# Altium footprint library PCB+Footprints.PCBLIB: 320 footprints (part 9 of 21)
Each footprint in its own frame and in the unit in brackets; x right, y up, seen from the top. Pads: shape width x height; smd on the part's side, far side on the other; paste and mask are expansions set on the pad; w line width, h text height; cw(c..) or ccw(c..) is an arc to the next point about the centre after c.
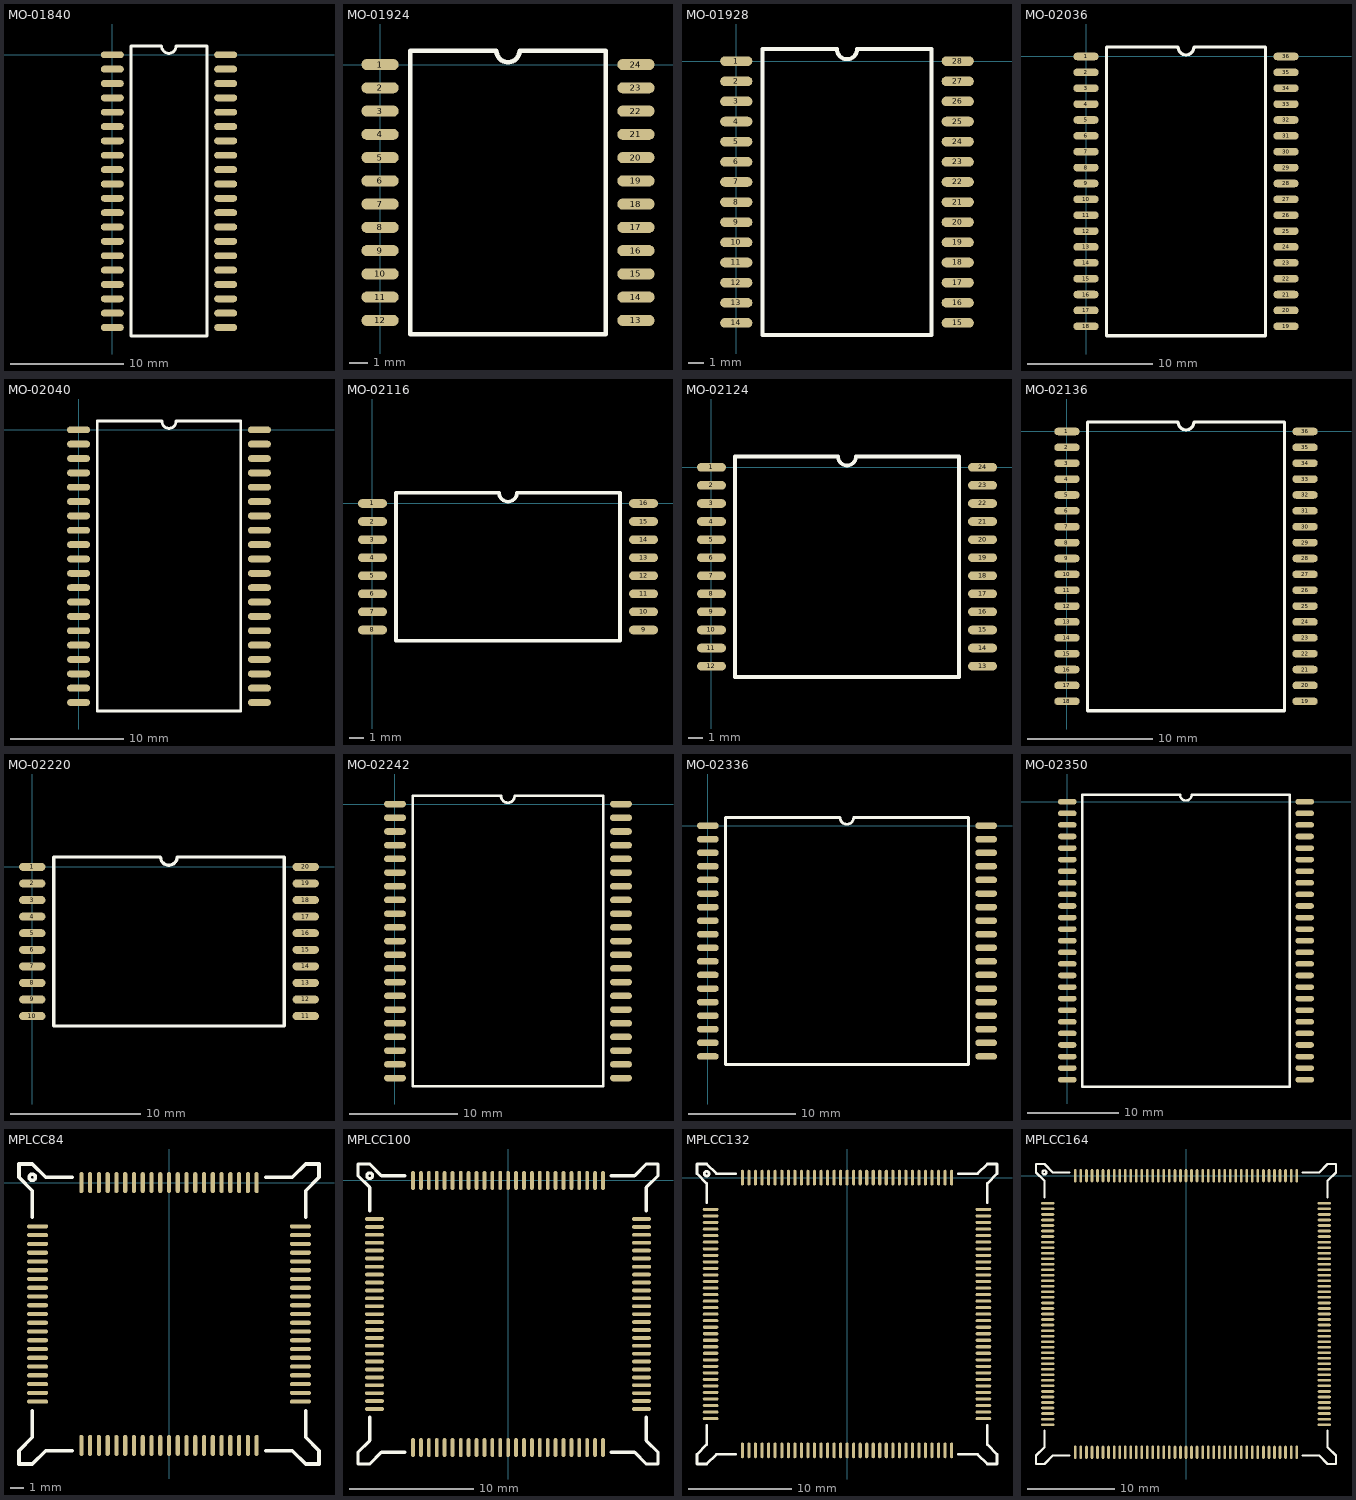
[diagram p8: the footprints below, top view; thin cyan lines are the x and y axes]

## MO-01840 [mil]
pads (40):
  oval 80x24 smd: 1(0,0) 2(0,-50) 3(0,-100) 4(0,-150) 5(0,-200) 6(0,-250) 7(0,-300) 8(0,-350) 9(0,-400) 10(0,-450) 11(0,-500) 12(0,-550) 13(0,-600) 14(0,-650) 15(0,-700) 16(0,-750) 17(0,-800) 18(0,-850) 19(0,-900) 20(0,-950) 21(395,-950) 22(395,-900) 23(395,-850) 24(395,-800) 25(395,-750) 26(395,-700) 27(395,-650) 28(395,-600) 29(395,-550) 30(395,-500) 31(395,-450) 32(395,-400) 33(395,-350) 34(395,-300) 35(395,-250) 36(395,-200) 37(395,-150) 38(395,-100) 39(395,-50) 40(395,0)
TopOverlay:
  lines w10: 65,-980 65,30 172,30 ccw(c197,30) 222,30 330,30 330,-980 65,-980

## MO-01924 [mil]
pads (24):
  oval 80x24 smd: 1(0,0) 2(0,-50) 3(0,-100) 4(0,-150) 5(0,-200) 6(0,-250) 7(0,-300) 8(0,-350) 9(0,-400) 10(0,-450) 11(0,-500) 12(0,-550) 13(550,-550) 14(550,-500) 15(550,-450) 16(550,-400) 17(550,-350) 18(550,-300) 19(550,-250) 20(550,-200) 21(550,-150) 22(550,-100) 23(550,-50) 24(550,0)
TopOverlay:
  lines w10: 65,-580 485,-580 485,30 300,30 cw(c275,30) 250,30 65,30 65,-580

## MO-01928 [mil]
pads (28):
  oval 80x24 smd: 1(0,0) 2(0,-50) 3(0,-100) 4(0,-150) 5(0,-200) 6(0,-250) 7(0,-300) 8(0,-350) 9(0,-400) 10(0,-450) 11(0,-500) 12(0,-550) 13(0,-600) 14(0,-650) 15(550,-650) 16(550,-600) 17(550,-550) 18(550,-500) 19(550,-450) 20(550,-400) 21(550,-350) 22(550,-300) 23(550,-250) 24(550,-200) 25(550,-150) 26(550,-100) 27(550,-50) 28(550,0)
TopOverlay:
  lines w10: 65,-680 485,-680 485,30 300,30 cw(c275,30) 250,30 65,30 65,-680

## MO-02036 [mil]
pads (36):
  oval 80x24 smd: 1(0,0) 2(0,-50) 3(0,-100) 4(0,-150) 5(0,-200) 6(0,-250) 7(0,-300) 8(0,-350) 9(0,-400) 10(0,-450) 11(0,-500) 12(0,-550) 13(0,-600) 14(0,-650) 15(0,-700) 16(0,-750) 17(0,-800) 18(0,-850) 19(630,-850) 20(630,-800) 21(630,-750) 22(630,-700) 23(630,-650) 24(630,-600) 25(630,-550) 26(630,-500) 27(630,-450) 28(630,-400) 29(630,-350) 30(630,-300) 31(630,-250) 32(630,-200) 33(630,-150) 34(630,-100) 35(630,-50) 36(630,0)
TopOverlay:
  lines w10: 65,-880 565,-880 565,30 340,30 cw(c315,30) 290,30 65,30 65,-880

## MO-02040 [mil]
pads (40):
  oval 80x24 smd: 1(0,0) 2(0,-50) 3(0,-100) 4(0,-150) 5(0,-200) 6(0,-250) 7(0,-300) 8(0,-350) 9(0,-400) 10(0,-450) 11(0,-500) 12(0,-550) 13(0,-600) 14(0,-650) 15(0,-700) 16(0,-750) 17(0,-800) 18(0,-850) 19(0,-900) 20(0,-950) 21(630,-950) 22(630,-900) 23(630,-850) 24(630,-800) 25(630,-750) 26(630,-700) 27(630,-650) 28(630,-600) 29(630,-550) 30(630,-500) 31(630,-450) 32(630,-400) 33(630,-350) 34(630,-300) 35(630,-250) 36(630,-200) 37(630,-150) 38(630,-100) 39(630,-50) 40(630,0)
TopOverlay:
  lines w10: 65,-980 565,-980 565,30 340,30 cw(c315,30) 290,30 65,30 65,-980

## MO-02116 [mil]
pads (16):
  oval 80x24 smd: 1(0,0) 2(0,-50) 3(0,-100) 4(0,-150) 5(0,-200) 6(0,-250) 7(0,-300) 8(0,-350) 9(750,-350) 10(750,-300) 11(750,-250) 12(750,-200) 13(750,-150) 14(750,-100) 15(750,-50) 16(750,0)
TopOverlay:
  lines w10: 65,-380 685,-380 685,30 400,30 cw(c375,30) 350,30 65,30 65,-380

## MO-02124 [mil]
pads (24):
  oval 80x24 smd: 1(0,0) 2(0,-50) 3(0,-100) 4(0,-150) 5(0,-200) 6(0,-250) 7(0,-300) 8(0,-350) 9(0,-400) 10(0,-450) 11(0,-500) 12(0,-550) 13(750,-550) 14(750,-500) 15(750,-450) 16(750,-400) 17(750,-350) 18(750,-300) 19(750,-250) 20(750,-200) 21(750,-150) 22(750,-100) 23(750,-50) 24(750,0)
TopOverlay:
  lines w10: 65,-580 685,-580 685,30 400,30 cw(c375,30) 350,30 65,30 65,-580

## MO-02136 [mil]
pads (36):
  oval 80x24 smd: 1(0,0) 2(0,-50) 3(0,-100) 4(0,-150) 5(0,-200) 6(0,-250) 7(0,-300) 8(0,-350) 9(0,-400) 10(0,-450) 11(0,-500) 12(0,-550) 13(0,-600) 14(0,-650) 15(0,-700) 16(0,-750) 17(0,-800) 18(0,-850) 19(750,-850) 20(750,-800) 21(750,-750) 22(750,-700) 23(750,-650) 24(750,-600) 25(750,-550) 26(750,-500) 27(750,-450) 28(750,-400) 29(750,-350) 30(750,-300) 31(750,-250) 32(750,-200) 33(750,-150) 34(750,-100) 35(750,-50) 36(750,0)
TopOverlay:
  lines w10: 65,-880 685,-880 685,30 400,30 cw(c375,30) 350,30 65,30 65,-880

## MO-02220 [mil]
pads (20):
  oval 80x24 smd: 1(0,0) 2(0,-50) 3(0,-100) 4(0,-150) 5(0,-200) 6(0,-250) 7(0,-300) 8(0,-350) 9(0,-400) 10(0,-450) 11(825,-450) 12(825,-400) 13(825,-350) 14(825,-300) 15(825,-250) 16(825,-200) 17(825,-150) 18(825,-100) 19(825,-50) 20(825,0)
TopOverlay:
  lines w10: 65,-480 760,-480 760,30 437,30 cw(c412,30) 387,30 65,30 65,-480

## MO-02242 [mil]
pads (42):
  oval 80x24 smd: 1(0,0) 2(0,-50) 3(0,-100) 4(0,-150) 5(0,-200) 6(0,-250) 7(0,-300) 8(0,-350) 9(0,-400) 10(0,-450) 11(0,-500) 12(0,-550) 13(0,-600) 14(0,-650) 15(0,-700) 16(0,-750) 17(0,-800) 18(0,-850) 19(0,-900) 20(0,-950) 21(0,-1000) 22(825,-1000) 23(825,-950) 24(825,-900) 25(825,-850) 26(825,-800) 27(825,-750) 28(825,-700) 29(825,-650) 30(825,-600) 31(825,-550) 32(825,-500) 33(825,-450) 34(825,-400) 35(825,-350) 36(825,-300) 37(825,-250) 38(825,-200) 39(825,-150) 40(825,-100) 41(825,-50) 42(825,0)
TopOverlay:
  lines w10: 65,-1030 760,-1030 760,30 437,30 cw(c412,30) 387,30 65,30 65,-1030

## MO-02336 [mil]
pads (36):
  oval 80x24 smd: 1(0,0) 2(0,-50) 3(0,-100) 4(0,-150) 5(0,-200) 6(0,-250) 7(0,-300) 8(0,-350) 9(0,-400) 10(0,-450) 11(0,-500) 12(0,-550) 13(0,-600) 14(0,-650) 15(0,-700) 16(0,-750) 17(0,-800) 18(0,-850) 19(1025,-850) 20(1025,-800) 21(1025,-750) 22(1025,-700) 23(1025,-650) 24(1025,-600) 25(1025,-550) 26(1025,-500) 27(1025,-450) 28(1025,-400) 29(1025,-350) 30(1025,-300) 31(1025,-250) 32(1025,-200) 33(1025,-150) 34(1025,-100) 35(1025,-50) 36(1025,0)
TopOverlay:
  lines w10: 65,-880 960,-880 960,30 537,30 cw(c512,30) 487,30 65,30 65,-880

## MO-02350 [mil]
pads (50):
  oval 80x24 smd: 1(0,0) 2(0,-50) 3(0,-100) 4(0,-150) 5(0,-200) 6(0,-250) 7(0,-300) 8(0,-350) 9(0,-400) 10(0,-450) 11(0,-500) 12(0,-550) 13(0,-600) 14(0,-650) 15(0,-700) 16(0,-750) 17(0,-800) 18(0,-850) 19(0,-900) 20(0,-950) 21(0,-1000) 22(0,-1050) 23(0,-1100) 24(0,-1150) 25(0,-1200) 26(1025,-1200) 27(1025,-1150) 28(1025,-1100) 29(1025,-1050) 30(1025,-1000) 31(1025,-950) 32(1025,-900) 33(1025,-850) 34(1025,-800) 35(1025,-750) 36(1025,-700) 37(1025,-650) 38(1025,-600) 39(1025,-550) 40(1025,-500) 41(1025,-450) 42(1025,-400) 43(1025,-350) 44(1025,-300) 45(1025,-250) 46(1025,-200) 47(1025,-150) 48(1025,-100) 49(1025,-50) 50(1025,0)
TopOverlay:
  lines w10: 65,-1230 960,-1230 960,30 537,30 cw(c512,30) 487,30 65,30 65,-1230

## MPLCC84 [mil]
pads (84):
  oval 12x60 smd: 1(0,0) 2(-25,0) 3(-50,0) 4(-75,0) 5(-100,0) 6(-125,0) 7(-150,0) 8(-175,0) 9(-200,0) 10(-225,0) 11(-250,0) 33(-250,-750) 34(-225,-750) 35(-200,-750) 36(-175,-750) 37(-150,-750) 38(-125,-750) 39(-100,-750) 40(-75,-750) 41(-50,-750) 42(-25,-750) 43(0,-750) 44(25,-750) 45(50,-750) 46(75,-750) 47(100,-750) 48(125,-750) 49(150,-750) 50(175,-750) 51(200,-750) 52(225,-750) 53(250,-750) 75(250,0) 76(225,0) 77(200,0) 78(175,0) 79(150,0) 80(125,0) 81(100,0) 82(75,0) 83(50,0) 84(25,0)
  oval 60x12 smd: 12(-375,-125) 13(-375,-150) 14(-375,-175) 15(-375,-200) 16(-375,-225) 17(-375,-250) 18(-375,-275) 19(-375,-300) 20(-375,-325) 21(-375,-350) 22(-375,-375) 23(-375,-400) 24(-375,-425) 25(-375,-450) 26(-375,-475) 27(-375,-500) 28(-375,-525) 29(-375,-550) 30(-375,-575) 31(-375,-600) 32(-375,-625) 54(375,-625) 55(375,-600) 56(375,-575) 57(375,-550) 58(375,-525) 59(375,-500) 60(375,-475) 61(375,-450) 62(375,-425) 63(375,-400) 64(375,-375) 65(375,-350) 66(375,-325) 67(375,-300) 68(375,-275) 69(375,-250) 70(375,-225) 71(375,-200) 72(375,-175) 73(375,-150) 74(375,-125)
TopOverlay:
  circle w10: c-390,15 r9
  lines w10: -390,-651 -390,-727 -428,-765 -428,-803 -390,-803 -352,-765 -276,-765 ; -390,-99 -390,-23 -428,15 -428,53 -390,53 -352,15 -276,15 ; 276,-765 352,-765 390,-803 428,-803 428,-765 390,-727 390,-651 ; 276,15 352,15 390,53 428,53 428,15 390,-23 390,-99

## MPLCC100 [mil]
pads (100):
  oval 12x60 smd: 1(0,0) 2(-25,0) 3(-50,0) 4(-75,0) 5(-100,0) 6(-125,0) 7(-150,0) 8(-176,0) 9(-201,0) 10(-226,0) 11(-251,0) 12(-276,0) 13(-301,0) 39(-301,-845) 40(-276,-845) 41(-251,-845) 42(-226,-845) 43(-201,-845) 44(-176,-845) 45(-150,-845) 46(-125,-845) 47(-100,-845) 48(-75,-845) 49(-50,-845) 50(-25,-845) 51(0,-845) 52(25,-845) 53(50,-845) 54(75,-845) 55(100,-845) 56(125,-845) 57(150,-845) 58(175,-845) 59(200,-845) 60(225,-845) 61(250,-845) 62(275,-845) 63(300,-845) 89(300,0) 90(275,0) 91(250,0) 92(225,0) 93(200,0) 94(175,0) 95(150,0) 96(125,0) 97(100,0) 98(75,0) 99(50,0) 100(25,0)
  oval 60x12 smd: 14(-423,-122) 15(-423,-147) 16(-423,-172) 17(-423,-197) 18(-423,-222) 19(-423,-247) 20(-423,-273) 21(-423,-298) 22(-423,-323) 23(-423,-348) 24(-423,-373) 25(-423,-398) 26(-423,-423) 27(-423,-448) 28(-423,-473) 29(-423,-498) 30(-423,-523) 31(-423,-548) 32(-423,-573) 33(-423,-598) 34(-423,-623) 35(-423,-648) 36(-423,-673) 37(-423,-698) 38(-423,-723) 64(422,-723) 65(422,-698) 66(422,-673) 67(422,-648) 68(422,-623) 69(422,-598) 70(422,-573) 71(422,-548) 72(422,-523) 73(422,-498) 74(422,-473) 75(422,-448) 76(422,-423) 77(422,-398) 78(422,-373) 79(422,-348) 80(422,-323) 81(422,-298) 82(422,-273) 83(422,-247) 84(422,-222) 85(422,-197) 86(422,-172) 87(422,-147) 88(422,-122)
TopOverlay:
  circle w10: c-438,15 r9
  lines w10: -438,-749 -438,-823 -475,-860 -475,-897 -438,-897 -401,-860 -327,-860 ; -438,-96 -438,-22 -475,15 -475,52 -438,52 -401,15 -327,15 ; 326,-860 400,-860 437,-897 474,-897 474,-860 437,-823 437,-749 ; 326,15 400,15 437,52 474,52 474,15 437,-22 437,-96

## MPLCC132 [mil]
pads (132):
  oval 12x60 smd: 1(0,0) 2(-25,0) 3(-50,0) 4(-75,0) 5(-100,0) 6(-125,0) 7(-150,0) 8(-175,0) 9(-200,0) 10(-225,0) 11(-250,0) 12(-276,0) 13(-301,0) 14(-326,0) 15(-351,0) 16(-376,0) 17(-401,0) 51(-401,-1045) 52(-376,-1045) 53(-351,-1045) 54(-326,-1045) 55(-301,-1045) 56(-276,-1045) 57(-250,-1045) 58(-225,-1045) 59(-200,-1045) 60(-175,-1045) 61(-150,-1045) 62(-125,-1045) 63(-100,-1045) 64(-75,-1045) 65(-50,-1045) 66(-25,-1045) 67(0,-1045) 68(25,-1045) 69(50,-1045) 70(75,-1045) 71(100,-1045) 72(125,-1045) 73(150,-1045) 74(175,-1045) 75(200,-1045) 76(225,-1045) 77(250,-1045) 78(275,-1045) 79(300,-1045) 80(325,-1045) 81(350,-1045) 82(375,-1045) 83(400,-1045) 117(400,0) 118(375,0) 119(350,0) 120(325,0) 121(300,0) 122(275,0) 123(250,0) 124(225,0) 125(200,0) 126(175,0) 127(150,0) 128(125,0) 129(100,0) 130(75,0) 131(50,0) 132(25,0)
  oval 60x12 smd: 18(-523,-122) 19(-523,-147) 20(-523,-172) 21(-523,-197) 22(-523,-222) 23(-523,-247) 24(-523,-273) 25(-523,-298) 26(-523,-323) 27(-523,-348) 28(-523,-373) 29(-523,-398) 30(-523,-423) 31(-523,-448) 32(-523,-473) 33(-523,-498) 34(-523,-523) 35(-523,-548) 36(-523,-573) 37(-523,-598) 38(-523,-623) 39(-523,-648) 40(-523,-673) 41(-523,-698) 42(-523,-723) 43(-523,-748) 44(-523,-773) 45(-523,-798) 46(-523,-823) 47(-523,-848) 48(-523,-873) 49(-523,-898) 50(-523,-923) 84(522,-923) 85(522,-898) 86(522,-873) 87(522,-848) 88(522,-823) 89(522,-798) 90(522,-773) 91(522,-748) 92(522,-723) 93(522,-698) 94(522,-673) 95(522,-648) 96(522,-623) 97(522,-598) 98(522,-573) 99(522,-548) 100(522,-523) 101(522,-498) 102(522,-473) 103(522,-448) 104(522,-423) 105(522,-398) 106(522,-373) 107(522,-348) 108(522,-323) 109(522,-298) 110(522,-273) 111(522,-247) 112(522,-222) 113(522,-197) 114(522,-172) 115(522,-147) 116(522,-122)
TopOverlay:
  circle w10: c-538,15 r9
  lines w10: -538,-949 -538,-1023 -575,-1060 -575,-1097 -538,-1097 -501,-1060 -427,-1060 ; -538,-96 -538,-22 -575,15 -575,52 -538,52 -501,15 -427,15 ; 426,-1060 500,-1060 537,-1097 574,-1097 574,-1060 537,-1023 537,-949 ; 426,15 500,15 537,52 574,52 574,15 537,-22 537,-96

## MPLCC164 [mil]
pads (164):
  oval 12x60 smd: 1(0,0) 2(-25,0) 3(-50,0) 4(-75,0) 5(-100,0) 6(-125,0) 7(-150,0) 8(-175,0) 9(-200,0) 10(-225,0) 11(-250,0) 12(-275,0) 13(-300,0) 14(-325,0) 15(-350,0) 16(-375,0) 17(-400,0) 18(-425,0) 19(-450,0) 20(-475,0) 21(-500,0) 63(-500,-1250) 64(-475,-1250) 65(-450,-1250) 66(-425,-1250) 67(-400,-1250) 68(-375,-1250) 69(-350,-1250) 70(-325,-1250) 71(-300,-1250) 72(-275,-1250) 73(-250,-1250) 74(-225,-1250) 75(-200,-1250) 76(-175,-1250) 77(-150,-1250) 78(-125,-1250) 79(-100,-1250) 80(-75,-1250) 81(-50,-1250) 82(-25,-1250) 83(0,-1250) 84(25,-1250) 85(50,-1250) 86(75,-1250) 87(100,-1250) 88(125,-1250) 89(150,-1250) 90(175,-1250) 91(200,-1250) 92(225,-1250) 93(250,-1250) 94(275,-1250) 95(300,-1250) 96(325,-1250) 97(350,-1250) 98(375,-1250) 99(400,-1250) 100(425,-1250) 101(450,-1250) 102(475,-1250) 103(500,-1250) 145(500,0) 146(475,0) 147(450,0) 148(425,0) 149(400,0) 150(375,0) 151(350,0) 152(325,0) 153(300,0) 154(275,0) 155(250,0) 156(225,0) 157(200,0) 158(175,0) 159(150,0) 160(125,0) 161(100,0) 162(75,0) 163(50,0) 164(25,0)
  oval 60x12 smd: 22(-625,-125) 23(-625,-150) 24(-625,-175) 25(-625,-200) 26(-625,-225) 27(-625,-250) 28(-625,-275) 29(-625,-300) 30(-625,-325) 31(-625,-350) 32(-625,-375) 33(-625,-400) 34(-625,-425) 35(-625,-450) 36(-625,-475) 37(-625,-500) 38(-625,-525) 39(-625,-550) 40(-625,-575) 41(-625,-600) 42(-625,-625) 43(-625,-650) 44(-625,-675) 45(-625,-700) 46(-625,-725) 47(-625,-750) 48(-625,-775) 49(-625,-800) 50(-625,-825) 51(-625,-850) 52(-625,-875) 53(-625,-900) 54(-625,-925) 55(-625,-950) 56(-625,-975) 57(-625,-1000) 58(-625,-1025) 59(-625,-1050) 60(-625,-1075) 61(-625,-1100) 62(-625,-1125) 104(625,-1125) 105(625,-1100) 106(625,-1075) 107(625,-1050) 108(625,-1025) 109(625,-1000) 110(625,-975) 111(625,-950) 112(625,-925) 113(625,-900) 114(625,-875) 115(625,-850) 116(625,-825) 117(625,-800) 118(625,-775) 119(625,-750) 120(625,-725) 121(625,-700) 122(625,-675) 123(625,-650) 124(625,-625) 125(625,-600) 126(625,-575) 127(625,-550) 128(625,-525) 129(625,-500) 130(625,-475) 131(625,-450) 132(625,-425) 133(625,-400) 134(625,-375) 135(625,-350) 136(625,-325) 137(625,-300) 138(625,-275) 139(625,-250) 140(625,-225) 141(625,-200) 142(625,-175) 143(625,-150) 144(625,-125)
TopOverlay:
  circle w10: c-640,15 r9
  lines w10: -640,-1151 -640,-1227 -678,-1265 -678,-1303 -640,-1303 -602,-1265 -526,-1265 ; -640,-99 -640,-23 -678,15 -678,53 -640,53 -602,15 -526,15 ; 526,-1265 602,-1265 640,-1303 678,-1303 678,-1265 640,-1227 640,-1151 ; 526,15 602,15 640,53 678,53 678,15 640,-23 640,-99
